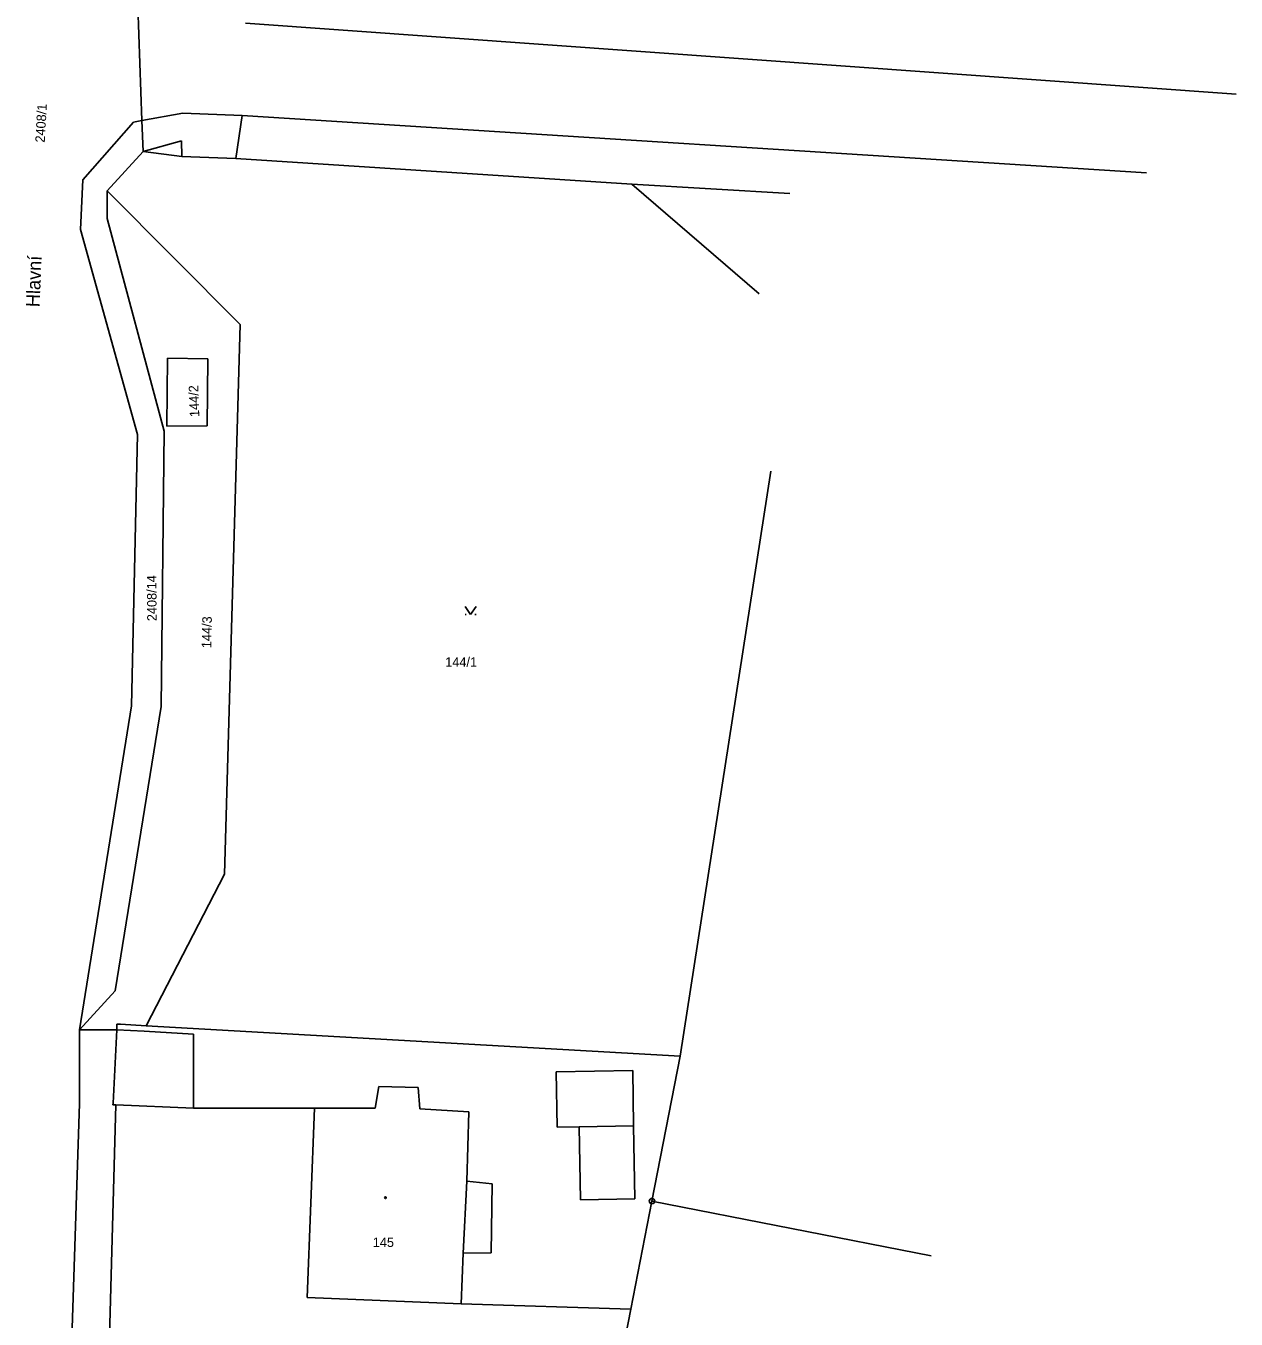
# Model space of a CAD drawing. Extents: x -454285 to -453563, y -1108687 to -1108249.
# Drawn here: x -453652.4 to -453563.3, y -1108571.7 to -1108476.5 of the extents above; entities that cross this region are included whole.
import ezdxf

# ---------------------------------------------------------------- set-up
doc = ezdxf.new("R2010")
doc.units = 0
for name, color, linetype in [('1', 7, 'Continuous'), ('14', 7, 'Continuous'), ('15', 7, 'Continuous'), ('16', 7, 'Continuous'), ('2', 7, 'Continuous'), ('23', 7, 'Continuous'), ('25', 7, 'Continuous'), ('28', 7, 'Continuous'), ('38', 7, 'Continuous')]:
    doc.layers.add(name, color=color, linetype=linetype)

# ---------------------------------------------------------------- blocks, each defined once
blk = doc.blocks.new('Z402')
for start, end in [(0, 180), (180, 0)]:
    blk.add_arc((0, 0), 0.15, start, end)
blk = doc.blocks.new('Z105')
for radius in [0.5, 0.01]:
    blk.add_circle((0, 0), radius)
blk = doc.blocks.new('Z3140')
for p, q in [((-1, 1.5), (0, 0)), ((-1, 0), (-0.8, 0)), ((0, 0), (1, 1.5)), ((0.8, 0), (1, 0))]:
    blk.add_line(p, q)

msp = doc.modelspace()

# ---------------------------------------------------------------- linework, layer by layer
at = {"layer": '1'}
for p, q in [((-453644.177, -1108475.001), (-453643.877, -1108483.451)), ((-453644.507, -1108483.571), (-453648.227, -1108487.811)), ((-453644.507, -1108483.571), (-453643.877, -1108483.451)), ((-453643.877, -1108483.451), (-453643.797, -1108485.731)), ((-453643.797, -1108485.731), (-453646.427, -1108488.631)), ((-453640.937, -1108486.091), (-453643.797, -1108485.731)), ((-453636.977, -1108486.251), (-453640.937, -1108486.091)), ((-453607.817, -1108488.121), (-453636.977, -1108486.251)), ((-453648.227, -1108487.811), (-453648.407, -1108491.461)), ((-453646.427, -1108488.631), (-453646.447, -1108490.671)), ((-453646.427, -1108488.631), (-453636.657, -1108498.451)), ((-453607.817, -1108488.121), (-453596.177, -1108488.831)), ((-453607.817, -1108488.121), (-453598.427, -1108496.191)), ((-453646.447, -1108490.671), (-453642.247, -1108506.311)), ((-453648.407, -1108491.461), (-453644.197, -1108506.551)), ((-453636.657, -1108498.451), (-453637.807, -1108538.901)), ((-453642.047, -1108505.931), (-453641.997, -1108500.941)), ((-453641.997, -1108500.941), (-453639.017, -1108500.991)), ((-453639.017, -1108500.991), (-453639.067, -1108505.921)), ((-453639.067, -1108505.921), (-453642.047, -1108505.931)), ((-453644.197, -1108506.551), (-453644.657, -1108526.531)), ((-453642.247, -1108506.311), (-453642.467, -1108526.561)), ((-453597.587, -1108509.261), (-453604.247, -1108552.311)), ((-453644.657, -1108526.531), (-453648.467, -1108550.371)), ((-453642.467, -1108526.561), (-453645.837, -1108547.501)), ((-453643.557, -1108550.071), (-453637.807, -1108538.901)), ((-453645.837, -1108547.501), (-453648.467, -1108550.371)), ((-453648.467, -1108550.371), (-453648.487, -1108555.791)), ((-453645.737, -1108550.361), (-453648.467, -1108550.371)), ((-453645.737, -1108550.361), (-453646.007, -1108555.761)), ((-453645.717, -1108549.951), (-453645.737, -1108550.361)), ((-453645.717, -1108549.951), (-453645.447, -1108549.961)), ((-453645.447, -1108549.961), (-453643.557, -1108550.071)), ((-453643.557, -1108550.071), (-453604.247, -1108552.311)), ((-453606.327, -1108562.971), (-453604.247, -1108552.311)), ((-453648.487, -1108555.791), (-453649.647, -1108591.661)), ((-453645.797, -1108555.891), (-453646.797, -1108591.781)), ((-453646.007, -1108555.761), (-453646.017, -1108555.891)), ((-453646.017, -1108555.891), (-453645.797, -1108555.891)), ((-453640.087, -1108556.121), (-453645.797, -1108555.891)), ((-453640.087, -1108556.121), (-453631.167, -1108556.131)), ((-453631.167, -1108556.131), (-453631.717, -1108570.071)), ((-453606.327, -1108562.971), (-453607.877, -1108570.931)), ((-453585.777, -1108567.001), (-453606.327, -1108562.971)), ((-453620.367, -1108570.521), (-453631.717, -1108570.071)), ((-453620.367, -1108570.521), (-453607.877, -1108570.931)), ((-453612.117, -1108592.681), (-453607.877, -1108570.931))]:
    msp.add_line(p, q, dxfattribs=at)
at = {"layer": '2'}
for p, q in [((-453563.317, -1108481.511), (-453636.257, -1108476.291)), ((-453640.857, -1108482.901), (-453643.877, -1108483.451)), ((-453636.487, -1108483.081), (-453640.857, -1108482.901)), ((-453636.977, -1108486.251), (-453636.487, -1108483.081)), ((-453569.907, -1108487.301), (-453636.487, -1108483.081)), ((-453640.967, -1108484.941), (-453643.797, -1108485.731)), ((-453640.937, -1108486.091), (-453640.967, -1108484.941)), ((-453645.737, -1108550.361), (-453643.707, -1108550.471)), ((-453640.087, -1108550.681), (-453643.707, -1108550.471)), ((-453640.087, -1108550.681), (-453640.087, -1108556.121)), ((-453613.387, -1108553.461), (-453607.747, -1108553.361)), ((-453613.317, -1108557.531), (-453613.387, -1108553.461)), ((-453607.747, -1108553.361), (-453607.677, -1108557.431)), ((-453626.697, -1108556.131), (-453626.427, -1108554.531)), ((-453626.427, -1108554.531), (-453623.547, -1108554.621)), ((-453623.547, -1108554.621), (-453623.417, -1108556.181)), ((-453631.167, -1108556.131), (-453626.697, -1108556.131)), ((-453623.417, -1108556.181), (-453619.807, -1108556.391)), ((-453619.807, -1108556.391), (-453619.967, -1108561.511)), ((-453611.677, -1108557.501), (-453613.317, -1108557.531)), ((-453607.677, -1108557.431), (-453611.677, -1108557.501)), ((-453611.587, -1108562.871), (-453611.677, -1108557.501)), ((-453607.677, -1108557.431), (-453607.587, -1108562.801)), ((-453619.967, -1108561.511), (-453620.217, -1108566.801)), ((-453619.967, -1108561.511), (-453618.087, -1108561.691)), ((-453618.087, -1108561.691), (-453618.157, -1108566.781)), ((-453607.587, -1108562.801), (-453611.587, -1108562.871)), ((-453620.217, -1108566.801), (-453620.367, -1108570.521)), ((-453618.157, -1108566.781), (-453620.217, -1108566.801))]:
    msp.add_line(p, q, dxfattribs=at)

# ---------------------------------------------------------------- block references
at = {"layer": '23', "xscale": 0.4, "yscale": 0.4000000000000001}
msp.add_blockref('Z3140', (-453619.677, -1108519.811), dxfattribs=at)
at = {"layer": '25', "xscale": 0.4, "yscale": 0.4000000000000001}
msp.add_blockref('Z402', (-453625.947, -1108562.721), dxfattribs=at)
at = {"layer": '28', "xscale": 0.4, "yscale": 0.4000000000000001}
msp.add_blockref('Z105', (-453606.327, -1108562.971), dxfattribs=at)

# ---------------------------------------------------------------- texts
at = {"layer": '14'}
for s, rotation, p in [('144/2', 92.07, (-453639.652, -1108505.256)), ('2408/14', 90.531, (-453642.787, -1108520.289)), ('144/3', 88.92, (-453638.775, -1108522.287))]:
    msp.add_text(s, height=0.7, rotation=rotation, dxfattribs=at).set_placement(p)
msp.add_text('144/1', height=0.7, dxfattribs=at).set_placement((-453621.547, -1108523.651))
at = {"layer": '15'}
msp.add_text('145', height=0.7, dxfattribs=at).set_placement((-453626.883, -1108566.351))
at = {"layer": '16'}
msp.add_text('2408/1', height=0.7, rotation=86.7539, dxfattribs=at).set_placement((-453651.037, -1108485.091))
at = {"layer": '38'}
msp.add_text('Hlavní', height=1, rotation=87.606, dxfattribs=at).set_placement((-453651.417, -1108497.201))

doc.saveas('drawing.dxf')
